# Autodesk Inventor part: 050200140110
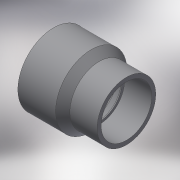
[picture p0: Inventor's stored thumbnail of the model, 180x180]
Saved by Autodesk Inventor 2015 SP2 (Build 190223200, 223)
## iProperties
Created: 2017-10
Part Number: 050200140110
Material: Generic
Description: PLASSON REDUCING SOCKET M.F.140(125)110 CEMENTED
Document SubType Name: Modeling
Designer: KIM
Density: 1 g/cm^3
Appearance: Default
Author: KIM
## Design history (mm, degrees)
derived "050200.ipt"
feature "Solid1::050200.ipt"
tag "TaggingFeature1"
body "Solid1"
other parameters: "d0" = 149, "d1" = 76, "d2" = 61, "d3" = 69, "d6" = 125, "d8" = 99, "d9" = 45 deg, "d12" = 1.25, "d_" = 125, "L_" = 76, "l_" = 69, "l_1" = 61, "H_" = 149, "d11" = 3.94791
